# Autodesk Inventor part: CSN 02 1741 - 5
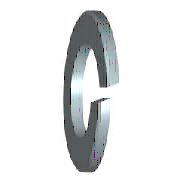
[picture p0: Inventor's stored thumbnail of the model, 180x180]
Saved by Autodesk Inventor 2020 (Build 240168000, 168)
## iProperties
Created: 2019-01
Part Number: CSN 02 1741 - 5
Material: Ocel, měkká
Description: Pružné podložky obdélníkového průřezu
Document SubType Name: Modeling
Standard: CSN 02 1741
Designer: doma
Standards Organization: CSN
Language: cs-CZ
Size Designation: 5
Categories: <MemberInstance><Categories><Category DisplayName="Spojovací materiál" InternalName="e4da775c-781d-43d5-af7c-5136215cf5a6" Mnemonic="FSTN"><Category DisplayName
Density: 7.85 g/cm^3
Appearance: Pololeštěná
IsCustomPart: 0
Author: doma
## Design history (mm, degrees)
sketch "Náčrt1"
  geometry: C1 r 4.35 at (0, 0); C2 r 2.55 at (0, 0); 1 further point
  constraints: 2 centre point, 2 coincident
  dimensions: "d0" = 5.1 diameter of C2 (= SD1); "d1" = 8.7 diameter of C1 (= SD2)
extrude "Těleso" new body sketch "Náčrt1" distance "d2" = 1.2 (= SD); taper "d3" = 0 deg
sketch "Náčrt2"
  geometry: L1 (0, -2.55)-(0, 2.55) reference; L2 (1.2, 4.35)-(1.2, -4.35) reference; L3 (-1.2, 0)-(7.2, 0) reference; L4 (0, -0.24)-(1.2, -0.028); L5 (0, 0.24)-(1.2, 0.452)
  constraints: 4 end point, 4 point on line, 1 parallel
  dimensions: "d4" = 0.24 distance from line of L3 L4.start (= 0.2 x SD); "d5" = 0.24 distance from line of L3 L5.start (= 0.2 x SD); "d6" = 80 deg angle of L2 L4 (= FAWI)
extrude "Výřez" cut sketch "Náčrt2" stored distance "d7" = 1.2 (= SD); taper "d8" = 0 deg
workaxis "Work Axis1"
workplane "Work Plane1"
body "Solid1"
other parameters: "SD1" = 5.1 [user parameter; used in 1 equation term], "SD2" = 8.7 [user parameter; used in 1 equation term], "SD" = 1.2 [user parameter; used in 4 equation terms], "FAWI" = 80 deg [user parameter; used in 1 equation term], "d9" = 0, "d10" = 0, "d11" = 0, "d12" = 0, "NND" = 5 [user parameter]
